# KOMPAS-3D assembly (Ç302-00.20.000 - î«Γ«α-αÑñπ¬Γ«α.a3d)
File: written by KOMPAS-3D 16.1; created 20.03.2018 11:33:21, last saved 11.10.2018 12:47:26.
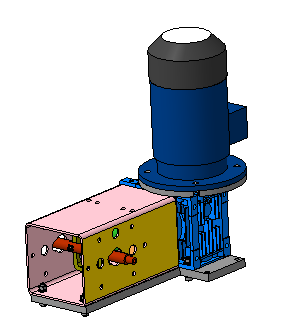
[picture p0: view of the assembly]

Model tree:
1. Массив по образцу:1
2. Экземпляр ( 1 )
3. Массив по концентрической сетке:1  (4 pattern instances)
     Шаг 2 = 360
4. Массив по сетке:1  (4 pattern instances)
     Шаг 1 = 130; Угол раствора = 90; Шаг 2 = 85; Номер 1 = 1
5. Массив по образцу:4  (2 pattern instances)
6. Сечение поверхностью:2
7. Сечение поверхностью:1  (labels: А302-00.20.000; C:\Program Files\ASCON\KOMPAS-3D V16\Sys\bo_atr.lat; C:\Program Files\ASCON\KOMPAS-3D V16\Sys\graphic.lyt)

Referenced files in Z:\1 ПКИ 3D\Редуктора NMRW\Редукторы\: Червячный мотор-редуктор NMRV063 АИР80.a3d
Referenced files in Z:\Мембранные насосы\Мембранный электропривод\А302-00.00.000 - ASTRA-302 (МЭ200)\3Д\: А302-00.20.001 - Основание.m3d, А302-00.35.000 - Фланец.a3d, А302-00.20.002 - Эксцентрик.m3d, А302-00.20.004 - Вал.m3d, А302-00.20.003 - Ползун.m3d
Referenced files in C:\Program Files\ASCON\KOMPAS-3D V16\Libs\PartLib\DATA\vault\Methods\Kompas\3D\: PLib_Check_spring_rings_GOST_13942_911.m3d, PLib_Washer_1_712.m3d, PLib_Screw_DIN_7984_1500.m3d, PLib_Key_prismatic_712.m3d
Referenced files in Z:\1 ПКИ 3D\1 Крепеж стандартный\Подшипник\: Подшипник 52х25х15 62052RSH SKF.m3d
Referenced files in C:\Program Files\ASCON\KOMPAS-3D V16\Libs\PartLib\DATA\VAULT\Methods\kompas\3d\: PLib_Bolt_1_900.m3d, PLib_Washer_2_712.m3d, PLib_Nut_OST92_900.m3d
Referenced files: GRAPHIC.TDP
Referenced files in \\192.168.87.28\Konstructor_doc\Мембранные насосы\Мембранный электропривод\А302-00.00.000 - ASTRA-302 (МЭ200)\Чертежи\: А302-00.35.000 - Фланец.cdw
Referenced files in Z:\Мембранные насосы\Мембранный электропривод\А302-00.00.000 - ASTRA-302 (МЭ200)\Чертежи\: А302-00.20.002 - Эксцентрик.cdw, А302-00.20.000  - Мотор-редуктор.spw
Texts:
  NMRV063 N P(кВт) V5
  P(мощн./дв.), i(передат. отн.) см. заказ
  Мотор-редуктор / NMRV063 N P(кВт) V5 / P(мощн./дв.), i(передат. отн.) см. заказ
  Двигатель1400 об/минN=1400/i
  Сталь 65Г ГОСТ 14959-79
  Кольцо A25.65Г ГОСТ 13942-86
  Isp3
  Подшипник 52х25х15 62052RSH SKF
  Сталь 20 ГОСТ 1050-2013
  Шайба C.5.04.019 ГОСТ 11371-78
  Болт М5-6gx35.58.019 ГОСТ 7805-70
  hole1
  hole2
  Сталь 30Х13 ГОСТ 5632-72
  Шайба 5 30Х13 019 ГОСТ 6402-70
  Гайка М5-6H.5.019 ГОСТ 5915-70
  bcut1
  hcut1
  cut1
  Шайба C.5.04.016 ГОСТ 11371-78
  Шайба C.8.04.019 ГОСТ 11371-78
  Шайба 8 30Х13 019 ГОСТ 6402-70
  Винт с цилиндрической головкой и шестигранным углублением под ключ ГОСТ Р ИСО 4762 - М8 x 20 - 6.8 - A9J
  Винт с цилиндрической головкой и шестигранным углублением под ключ ГОСТ Р ИСО 4762 - М8 x 35 - 6.8 - A9J
  Гайка М8-6H.5.019 ГОСТ 5915-70
  Винт с цилиндрической головкой и шестигранным углублением под ключ ГОСТ Р ИСО 4762 - М8 x 40 - 6.8 - A9J
  Шпонка 8x7x90 ГОСТ 23360-78
  skr2
  skr1
  Шпонка 8 x 7 x 90 ГОСТ 23360-78
  Крепежное изделие ГОСТ
  Винт с цилиндрической головкой и
  шестигранным углублением под ключ
  ГОСТ Р ИСО  4762-М8 x 20-6.8-A9J
  Винт с цилиндрической головкой и шестигранным углублением под ключ
  ГОСТ Р ИСО  4762-М8 x 35-6.8-A9J
  Винт с цилиндрической головкой и шестигранным углублением под ключ ГОСТ Р ИСО  4762-М8 x 35-6.8-A9J
  Body Specification ( left align )
  Body Specificaton ( centered )
  ГОСТ 13942-86
  ГОСТ 11371-78
  ГОСТ 7805-70
  М5-6gx35.58.019
  ГОСТ 6402-70
  ГОСТ 5915-70
  ГОСТ Р ИСО 4762-2012
  ГОСТ 23360-78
